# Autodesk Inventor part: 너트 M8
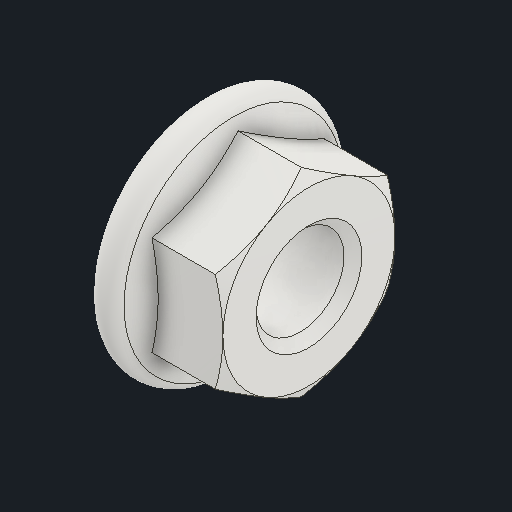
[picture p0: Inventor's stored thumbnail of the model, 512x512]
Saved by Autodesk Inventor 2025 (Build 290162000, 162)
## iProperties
Created: 2025-08
Part Number: 너트 M8
Material: 스테인리스강
Description: 플랜지붙이 6각 너트 - 일반 스레드
Document SubType Name: Modeling
Designer: infra002
Density: 8 g/cm^3
Appearance: 기본값
Author: jhkim
Sending System: Autodesk Inventor 2026
Preprocessor: ST-DEVELOPER v20.1
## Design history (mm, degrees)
feature "Solid1"
node "솔리드1"
